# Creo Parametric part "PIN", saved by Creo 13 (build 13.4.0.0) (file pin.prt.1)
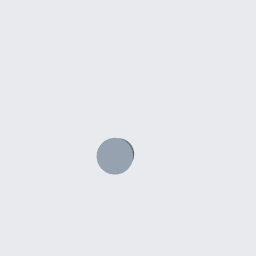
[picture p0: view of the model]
Units: millimeter Newton Second (mmNs); MM, TONNE, SECS
Materials in the file: TOOL_STEEL_AIR_HARDENING

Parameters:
  PTC_MATERIAL_NAME = "TOOL_STEEL_AIR_HARDENING"
  GRANTA_DATALINK_VERSION = "5"
  GRANTA_DATABASE_KEY = "Granta_Typical_Materials"
  GRANTA_IDENTITY_GUID = "47125d86-2419-4620-91c2-75fb533a2575"
  GRANTA_VERSION_GUID = "491ebe9b-4f26-4c69-bc7c-a150e396a778"
  GRANTA_MODEL_REFERENCE = "00000000-0000-0000-0000-000000000000"

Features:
  1. datum plane "RIGHT"
  2. datum plane "TOP"
  3. datum plane "FRONT"
  4. coordinate system
  5. curve
  6. protrusion

Surfaces: 2 plane, 1 cylinder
